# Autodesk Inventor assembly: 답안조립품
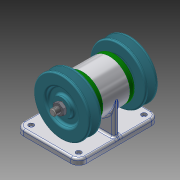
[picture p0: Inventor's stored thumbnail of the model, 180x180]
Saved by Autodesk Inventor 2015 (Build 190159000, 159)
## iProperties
Created: 2019-09
Part Number: 답안조립품
Document SubType Name: Assembly
Designer: LINEART-SSD.D4.16.07
Author: LINEART-SSD.D4.16.07
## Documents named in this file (10)
- C:\Users\LINEART-SSD.D4.16.07\Desktop\490904V1049\답안조립품.iam
- C:\Users\LINEART-SSD.D4.16.07\Desktop\490904V1049\본체.ipt
- C:\Users\LINEART-SSD.D4.16.07\Desktop\490904V1049\축.ipt
- C:\Users\LINEART-SSD.D4.16.07\Desktop\490904V1049\베어링 6004.ipt
- C:\Users\LINEART-SSD.D4.16.07\Desktop\490904V1049\커버.ipt
- C:\Users\LINEART-SSD.D4.16.07\Desktop\490904V1049\오일 실 17 30 5.ipt
- C:\Users\LINEART-SSD.D4.16.07\Desktop\490904V1049\볼트 M4.ipt
- C:\Users\LINEART-SSD.D4.16.07\Desktop\490904V1049\키 5 x 5 x 12.ipt
- C:\Users\LINEART-SSD.D4.16.07\Desktop\490904V1049\V-벨트풀리.ipt
- C:\Users\LINEART-SSD.D4.16.07\Desktop\490904V1049\너트 M10x1.ipt
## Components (2 placed, 1 different names)
1. V-벨트풀리:1 — 각도:9
2. V-벨트풀리:2 — 각도:10
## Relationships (2: Angle 2)
- 각도:9 [Angle]: V-벨트풀리:1
- 각도:10 [Angle]: V-벨트풀리:2
